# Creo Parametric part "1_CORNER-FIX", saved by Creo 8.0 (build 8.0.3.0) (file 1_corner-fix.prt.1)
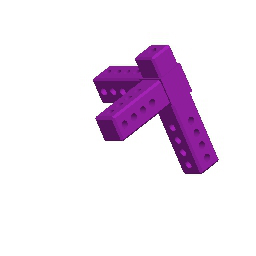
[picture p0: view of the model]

Other parameters: D51, D35, D27, D19, D5

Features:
  1. datum plane "RIGHT"
  2. datum plane "TOP"
  3. datum plane "FRONT"
  4. coordinate system
  5. protrusion
  6. protrusion
  7. pattern
  8. cut
  9. cut
  10. cut
  11. cut
  12. protrusion
  13. protrusion
  14. protrusion
  15. pattern
  16. cut
  17. cut
  18. cut
  19. cut
  20. pattern
  21. cut
  22. cut
  23. cut
  24. cut
  25. pattern
  26. cut
  27. cut
  28. cut
  29. cut
  30. pattern
  31. cut
  32. cut
  33. cut
  34. cut
  35. pattern
  36. cut
  37. cut
  38. cut
  39. cut
  40. chamfer
  41. chamfer
  42. round
  43. chamfer
  44. cut
  45. chamfer

Layers: 0_ALL_AXIS, 0_ALL_CSYS, 0_ALL_CURVES, 0_ALL_PLANES, 0_ALL_POINTS, 0_ALL_SURFS, JIAOZUO

Surfaces: 61 plane, 26 cylinder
